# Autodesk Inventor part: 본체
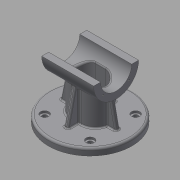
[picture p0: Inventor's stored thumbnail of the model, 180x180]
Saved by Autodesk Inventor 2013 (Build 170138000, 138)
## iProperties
Created: 2015-12
Part Number: 본체
Material: 일반
Document SubType Name: Modeling
Designer: mduedu
Density: 1 g/cm^3
Mass: 208.121 g
Surface Area: 536.241 cm^2
Volume: 208.121 cm^3
Author: mduedu
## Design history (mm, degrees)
sketch "스케치1"
  geometry: L1 (45, 40)-(-45, 40); L2 (-45, 40)-(-45, -40); L3 (-45, -40)-(45, -40); L4 (45, -40)-(45, 40); L5 (45, 40)-(-45, -40); L6 (-45, 40)-(45, -40); 2 further points
  constraints: 12 end point, 2 midpoint, 2 parallel, 1 coincident, 1 horizontal, 1 perpendicular, 3 other
  dimensions: "d0" = 90 distance of L2.end L3.end; "d2" = 80 distance of L1.end L2.end
extrude "돌출1" new body sketch "스케치1" distance "d3" = 10; taper "d4" = 0 deg
sketch "스케치2"
  geometry: C1 r 32.5 at (80, 0); 1 further point
  constraints: 1 centre point
  dimensions: "d5" = 65 diameter of C1; "d116" = 80 distance of point (0, 0) C1.centre
extrude "돌출2" join sketch "스케치2" stored distance "d7" = 75; taper "d8" = 0 deg
sketch "스케치3"
  geometry: L1 (-27.5, -20)-(27.5, -20); L2 (27.5, -20)-(27.5, 20); L3 (27.5, 20)-(-27.5, 20); L4 (-27.5, 20)-(-27.5, -20); L5 (-27.5, -20)-(27.5, 20); L6 (27.5, -20)-(-27.5, 20); 1 further point
  constraints: 12 end point, 2 midpoint, 2 parallel, 1 horizontal, 1 perpendicular
  dimensions: "d9" = 55 distance of L2.end L3.end; "d11" = 40 distance of L1.end L2.end
extrude "돌출3" new body sketch "스케치3" stored distance "d12" = 75; taper "d13" = 0 deg
fillet "모깎기1"
fillet "모깎기2"
feature "결합1"
  node "솔리드2"
sketch "스케치4"
  geometry: L1 (-37.5, 47.5)-(37.5, 47.5) reference; L2 (32.5, 47.5)-(40.208, 10); L3 (37.5, 47.5)-(37.5, 112.5) reference; L4 (60.208, 0)-(60.208, 10) reference; L5 (60.208, 10)-(-60.208, 10) reference; 1 further point
  constraints: 2 end point, 2 point on line
  dimensions: "d15" = 5 distance from line of L2.start L3; "d117" = 20 distance from line of L2.end L4
sketch "스케치5"
  geometry: L1 (10, 35.208)-(58.179, 24.085); L2 (0, 60.208)-(10, 60.208) reference; L3 (10, -60.208)-(10, 60.208) reference; 2 further points
  constraints: 2 end point, 1 point on line, 2 other
  dimensions: "d118" = 25 distance from line of L1.start L2; "d119" = 77 deg angle of L1 L3
feature "리브1" dims "d19" = 1, "d20" = 6, "d21" = 0, "d22" = 0, "d23" = 1, "d24" = 1
feature "리브2" dims "d25" = 1, "d26" = 6, "d27" = 0, "d28" = 0, "d29" = 1, "d30" = 1
fillet "모깎기4" dims "d31" = 2
fillet "모깎기5" dims "d32" = 2
fillet "모깎기16" dims "d149" = 2
sketch "스케치6"
  geometry: L1 (0, 0)-(-32.88, 32.88); L2 (0, 0)-(-46.5, 0); A1 r 46.5 centre (0, 0) between (-32.88, 32.88) and (-46.5, 0); 5 further points
  constraints: 4 end point, 2 coincident, 2 point on circle, 1 centre point, 1 horizontal, 5 other
  dimensions: "d120" = 93 diameter of A1; "d122" = 45 deg angle of L1 L2; "d126" = 360 deg dimension on point (0, 0) point (-32.88, 32.88) (derived)
hole "구멍1" sketch "스케치6" at (-32.88, 32.88), (-32.88, -32.88), (32.88, -32.88), (32.88, 32.88) diameter "d34" = 7; stored, may be unused: countersink angle "d38" = 90 deg, drill point angle "d40" = 118 deg; dims "d35" = 6, "d36" = 12, "d37" = 3, "d39" = 8
fillet "모깎기13" dims "d131" = 3
hole "구멍2" diameter "d44" = 45; stored, may be unused: countersink angle "d48" = 90 deg, drill point angle "d50" = 118 deg; dims "d42" = 10, "d43" = 10, "d45" = 6, "d46" = 4, "d47" = 2, "d49" = 8
sketch "스케치7" dims "d52" = 26.5
  geometry: L1 (0, 0)-(32.5, 0); L2 (0, 0)-(22.981, 22.981); A1 r 32.5 centre (0, 0) between (32.5, 0) and (22.981, 22.981) reference; 3 further points
  constraints: 4 end point, 2 point on circle, 1 coincident, 1 horizontal, 1 point on line, 3 other
  dimensions: "d51" = 45 deg angle of L2 L1
hole "구멍3" sketch "스케치7" at (18.738, 18.738) diameter "d54" = 2.459; stored, may be unused: countersink angle "d58" = 90 deg, drill point angle "d60" = 118 deg; dims "d55" = 8, "d56" = 4, "d57" = 2, "d59" = 10
sketch "스케치9"
  geometry: L1 (-75, 82.5)-(75, 82.5); L2 (75, 82.5)-(75, 0); L3 (75, 0)-(-75, 0); L4 (-75, 0)-(-75, 82.5); C1 r 32.5 at (0, 0) reference; 2 further points
  constraints: 8 end point, 2 parallel, 1 coincident, 1 horizontal, 1 midpoint, 1 perpendicular
  dimensions: "d71" = 50 distance edge to line of C1 L1; "d148" = 150 distance of L1.start L1.end
extrude "돌출5" cut sketch "스케치9" stored distance "d73" = 0; taper "d74" = 0 deg
node "작업 평면1"
sketch "스케치10"
  geometry: L1 (-7.5, 15)-(7.5, 15); L2 (-7.5, -15)-(7.5, -15); A1 r 15 centre (-7.5, 0) between (-7.5, 15) and (-7.5, -15); A2 r 15 centre (7.5, 0) between (7.5, -15) and (7.5, 15); A3 r 20 centre (-7.5, 0) between (-7.5, 20) and (-26.977, 4.545) reference; A4 r 20 centre (7.5, 0) between (26.977, 4.545) and (7.5, 20) reference; 1 further point
  constraints: 7 point on circle, 4 end point, 4 tangent, 3 point on line, 2 centre point, 2 horizontal, 1 concentric
  dimensions: "d150" = 5 radial gap between concentric circles of A1 A3; "d151" = 5 radial gap between concentric circles of A2 A4
extrude "돌출6" cut sketch "스케치10" stored distance "d78" = 50; taper "d79" = 0 deg
fillet "모깎기10" dims "d80" = 3
sketch "스케치11"
  geometry: 2 further points
  constraints: 1 coincident
hole "구멍4" sketch "스케치11" at (0, 0) diameter "d81" = 11; stored, may be unused: countersink angle "d85" = 90 deg, drill point angle "d87" = 118 deg; dims "d82" = 8, "d83" = 40, "d84" = 10, "d86" = 10
sketch "스케치12"
  geometry: C1 r 12 at (0, 0); 1 further point
  constraints: 1 centre point, 1 coincident
  dimensions: "d88" = 24 diameter of C1
extrude "돌출7" cut sketch "스케치12" distance "d89" = 5; taper "d90" = 0 deg
chamfer "모따기1" distance "d91" = 1; stored, may be unused: second distance "d92" = 2, angle "d93" = 45 deg
fillet "모깎기11" dims "d94" = 0.5
fillet "모깎기12" dims "d115" = 0.3
node "작업 평면3"
sketch "스케치17"
  geometry: 2 further points
  constraints: 1 horizontal alignment, 1 other
  dimensions: "d154" = 3.5 distance of point (-3.5, 0) point (0, 0)
feature "엠보싱1" sketch "스케치17" dims "d155" = 0.5, "d156" = 0
node "솔리드1"
mirror "대칭1"
mirror "대칭2"
pattern_circular "원형 패턴1" dims angle "d62" = 360 deg
mirror "대칭3"
